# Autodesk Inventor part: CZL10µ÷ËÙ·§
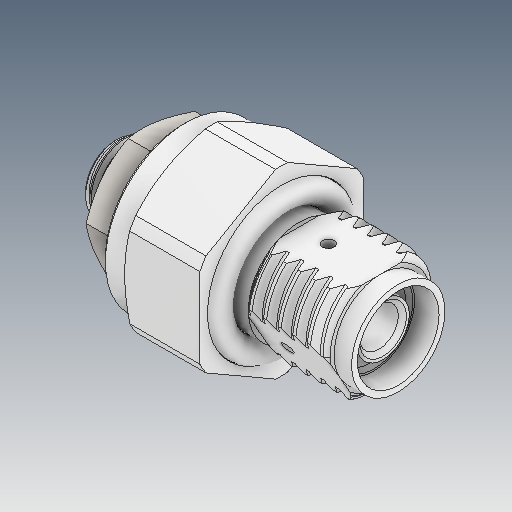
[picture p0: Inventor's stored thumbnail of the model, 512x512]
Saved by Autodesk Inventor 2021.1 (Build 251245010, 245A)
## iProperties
Created: 2021-05
Part Number: CZL10µ÷ËÙ·§
Material: Ogólny
Document SubType Name: Modeling
Designer: user
Density: 1 g/cm^3
Appearance: Domyślna
Author: user
Revision Number: ÈÎºÎ
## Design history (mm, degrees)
feature "ÊäÈë2"
feature "ÊäÈë4"
feature "ÊäÈë5"
node "Bryła1"
node "Bryła2"
node "Bryła3"
